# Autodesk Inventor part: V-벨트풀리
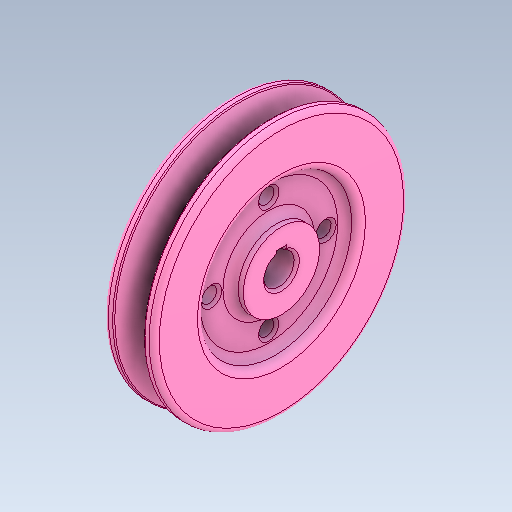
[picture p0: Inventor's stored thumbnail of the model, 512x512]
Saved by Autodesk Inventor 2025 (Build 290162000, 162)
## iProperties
Created: 2024-07
Part Number: V-벨트풀리
Material: 강철, 연강
Document SubType Name: Modeling
Designer: 미서니
Density: 7.86 g/cm^3
Appearance: 기본값
Author: jhkim
Sending System: Autodesk Inventor 2025
Preprocessor: ST-DEVELOPER v20
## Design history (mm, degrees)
feature "솔리드1"
node "솔리드2"
